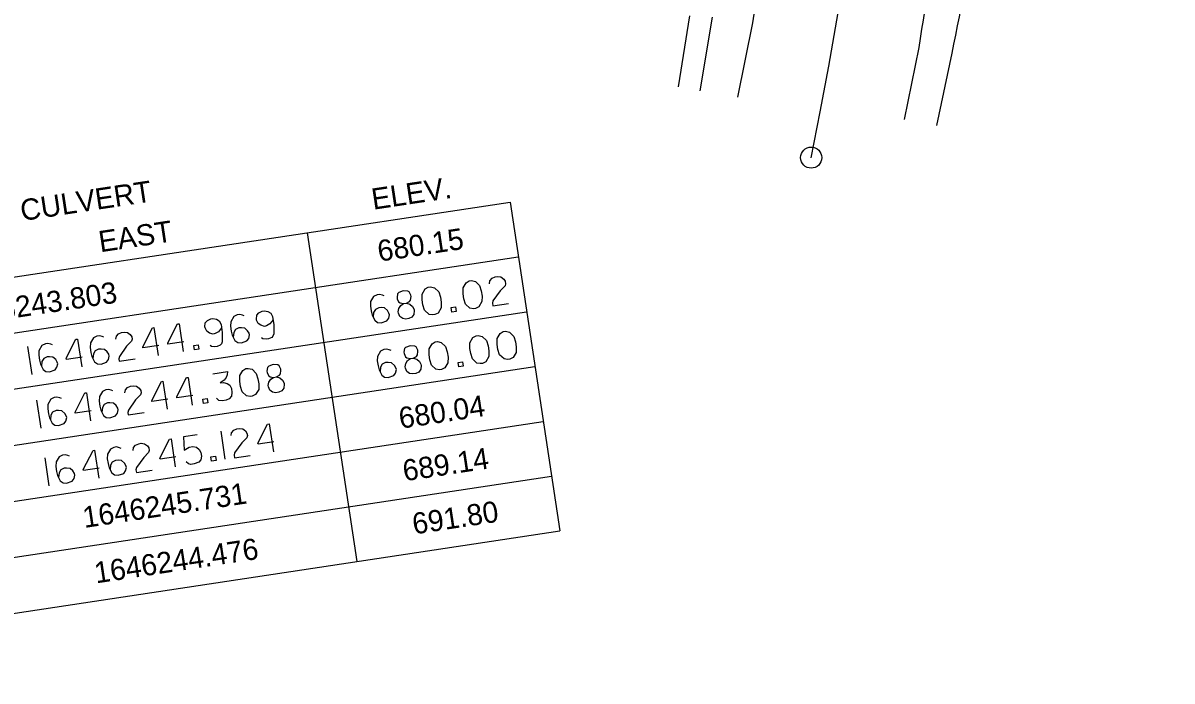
# Model space of a CAD drawing. Extents: x 1645945 to 2447332, y 713118 to 970361.
# Drawn here: x 1646189.7 to 1646352.4, y 969034 to 969127.2 of the extents above; entities that cross this region are included whole.
import ezdxf

# ---------------------------------------------------------------- set-up
doc = ezdxf.new("R2010")
doc.units = 0
for name, color, linetype in [('Exist Horizontal Alignment', 7, 'Continuous'), ('Exist Horizontal Alignment Station Label', 7, 'Continuous'), ('Exist Roads Curbs', 7, 'Continuous'), ('Exist Roads EOP', 7, 'Continuous'), ('Exist Roads EOT', 7, 'Continuous'), ('Exist Structure Major Bridge WW', 7, 'Continuous'), ('Exist Structure Major Bridge WW Text', 7, 'Continuous')]:
    doc.layers.add(name, color=color, linetype=linetype)

msp = doc.modelspace()

# ---------------------------------------------------------------- linework, layer by layer
at = {"layer": 'Exist Horizontal Alignment'}
msp.add_arc((1645516.89, 969265.29), 800, 348.6692, 18.755, dxfattribs=at)
at = {"layer": 'Exist Horizontal Alignment Station Label'}
msp.add_circle((1646301.3, 969108.12), 1.5, dxfattribs=at)
at = {"layer": 'Exist Roads Curbs'}
msp.add_line((1646282.51, 969118.14), (1646284.14, 969128.2), dxfattribs=at)
at = {"layer": 'Exist Roads EOP'}
for p, q in [((1646285.57, 969117.57), (1646287.33, 969128.01)), ((1646321.21, 969122.91), (1646319.04, 969112.67))]:
    msp.add_line(p, q, dxfattribs=at)
msp.add_spline([(1646379.88, 969432.02), (1646359.09, 969426.37), (1646353.34, 969423.7), (1646346.05, 969418.75), (1646333.89, 969406.7), (1646326.81, 969393.02), (1646325.09, 969385.45), (1646325.5, 969379.16), (1646330.03, 969336.13), (1646333.52, 969294.46), (1646334.18, 969250.57), (1646332.28, 969209.59), (1646328.48, 969164.09), (1646321.21, 969122.91)], degree=3, dxfattribs=at)
at = {"layer": 'Exist Roads EOT'}
for p, q in [((1646290.93, 969116.66), (1646293.03, 969127.18)), ((1646316.52, 969123.72), (1646314.47, 969113.51))]:
    msp.add_line(p, q, dxfattribs=at)
for points in [[(1646352.39, 969425.32), (1646344.68, 969420.87), (1646331.6, 969408.76), (1646323.81, 969394.56), (1646321.79, 969386.09), (1646321.5, 969379.49), (1646325.71, 969335.59), (1646328.02, 969294.74), (1646328.47, 969250.99), (1646326.96, 969209.87), (1646322.68, 969164.82), (1646316.52, 969123.72)], [(1646293.03, 969127.18), (1646298.98, 969166.96), (1646303.15, 969211.21), (1646304.61, 969249.63), (1646304.29, 969293.94), (1646302.47, 969332.58), (1646298.43, 969374.41), (1646292.35, 969414.45)]]:
    msp.add_spline(points, degree=3, dxfattribs=at)
at = {"layer": 'Exist Structure Major Bridge WW'}
for p, q in [((1646117.89, 969080.56), (1646258.66, 969101.81)), ((1646258.66, 969101.81), (1646265.69, 969055.26)), ((1646229.94, 969097.47), (1646236.96, 969050.93)), ((1646119.06, 969072.8), (1646259.83, 969094.05)), ((1646120.23, 969065.05), (1646261.01, 969086.29)), ((1646121.4, 969057.29), (1646262.18, 969078.54)), ((1646122.57, 969049.53), (1646263.35, 969070.78)), ((1646123.74, 969041.78), (1646264.52, 969063.02)), ((1646124.91, 969034.02), (1646265.69, 969055.26))]:
    msp.add_line(p, q, dxfattribs=at)
at = {"layer": 'Exist Structure Major Bridge WW Text'}
for p, q in [((1646191, 969077.42), (1646190.4, 969081.37)), ((1646192.27, 969069.82), (1646191.67, 969073.77)), ((1646218.34, 969065.43), (1646217.74, 969069.38)), ((1646193.42, 969061.67), (1646192.83, 969065.62))]:
    msp.add_line(p, q, dxfattribs=at)
for points in [[(1646252.88, 969090.67), (1646253.19, 969090.72), (1646253.75, 969090.58), (1646254.35, 969090), (1646254.59, 969089.24), (1646254.7, 969088.52), (1646254.69, 969087.73), (1646254.26, 969086.99), (1646253.79, 969086.76), (1646253.48, 969086.72), (1646252.99, 969086.8), (1646252.36, 969087.37), (1646252.11, 969088.13), (1646252.01, 969088.85), (1646252.01, 969089.68), (1646252.44, 969090.41), (1646252.88, 969090.67)], [(1646255.74, 969090.27), (1646255.81, 969090.67), (1646256.11, 969091.03), (1646256.55, 969091.22), (1646256.9, 969091.28), (1646257.38, 969091.22), (1646257.78, 969090.93), (1646257.98, 969090.61), (1646258.04, 969090.27), (1646257.95, 969089.97), (1646257.26, 969089.26), (1646256.24, 969087.83), (1646256.16, 969087.5), (1646256.22, 969087.13), (1646258.46, 969087.47)], [(1646240.84, 969088.57), (1646240.6, 969088.66), (1646240.2, 969088.76), (1646239.83, 969088.7), (1646239.35, 969088.47), (1646238.92, 969087.74), (1646238.89, 969087.09), (1646239, 969086.41), (1646239.15, 969085.83), (1646239.52, 969085.09), (1646239.91, 969084.79), (1646240.43, 969084.75), (1646241.21, 969085.02), (1646241.48, 969085.38), (1646241.59, 969085.88), (1646241.52, 969086.12), (1646241.31, 969086.47), (1646240.91, 969086.83), (1646240.42, 969086.88), (1646240.08, 969086.86), (1646239.6, 969086.63), (1646239.35, 969086.21), (1646239.28, 969085.56)], [(1646243.99, 969087.51), (1646244.43, 969087.74), (1646244.59, 969087.95), (1646244.65, 969088.44), (1646244.62, 969088.63), (1646244.39, 969089.1), (1646244.18, 969089.2), (1646243.54, 969089.26), (1646242.91, 969089.01), (1646242.74, 969088.85), (1646242.66, 969088.33), (1646242.68, 969088.14), (1646242.88, 969087.7), (1646243.1, 969087.54), (1646243.59, 969087.45), (1646243.99, 969087.51), (1646244.49, 969087.37), (1646244.86, 969087.04), (1646245.08, 969086.63), (1646245.1, 969086.47), (1646245.06, 969085.92), (1646244.77, 969085.53), (1646244.35, 969085.34), (1646243.91, 969085.27), (1646243.46, 969085.33), (1646243.07, 969085.62), (1646242.87, 969086.1), (1646242.84, 969086.29), (1646242.93, 969086.75), (1646243.18, 969087.17), (1646243.59, 969087.45)], [(1646247.09, 969089.8), (1646247.4, 969089.84), (1646247.96, 969089.7), (1646248.56, 969089.13), (1646248.8, 969088.37), (1646248.91, 969087.65), (1646248.9, 969086.85), (1646248.47, 969086.12), (1646247.99, 969085.89), (1646247.68, 969085.84), (1646247.19, 969085.93), (1646246.56, 969086.5), (1646246.32, 969087.26), (1646246.21, 969087.98), (1646246.22, 969088.8), (1646246.65, 969089.54), (1646247.09, 969089.8)], [(1646250.33, 969086.88), (1646250.95, 969086.97), (1646251.05, 969086.35), (1646250.42, 969086.25), (1646250.33, 969086.88)], [(1646217.81, 969084.04), (1646217.39, 969083.47), (1646216.92, 969083.21), (1646216.61, 969083.13), (1646216.11, 969083.28), (1646215.72, 969083.54), (1646215.49, 969084.01), (1646215.47, 969084.17), (1646215.51, 969084.72), (1646215.81, 969085.05), (1646216.29, 969085.28), (1646216.6, 969085.33), (1646217.09, 969085.24), (1646217.5, 969085.02), (1646217.74, 969084.51), (1646217.91, 969083.36), (1646217.91, 969082.94), (1646217.92, 969082.05), (1646217.81, 969081.75), (1646217.64, 969081.57), (1646217.19, 969081.37), (1646216.88, 969081.32), (1646216.4, 969081.38), (1646216.19, 969081.51)], [(1646221.03, 969085.71), (1646220.79, 969085.8), (1646220.4, 969085.9), (1646220.02, 969085.84), (1646219.55, 969085.61), (1646219.12, 969084.88), (1646219.09, 969084.24), (1646219.19, 969083.55), (1646219.34, 969082.97), (1646219.71, 969082.23), (1646220.1, 969081.94), (1646220.62, 969081.89), (1646221.41, 969082.17), (1646221.67, 969082.52), (1646221.79, 969083.02), (1646221.72, 969083.26), (1646221.51, 969083.61), (1646221.1, 969083.97), (1646220.62, 969084.02), (1646220.27, 969084), (1646219.79, 969083.77), (1646219.54, 969083.35), (1646219.48, 969082.7)], [(1646225.1, 969085.14), (1646224.67, 969084.57), (1646224.2, 969084.31), (1646223.9, 969084.23), (1646223.4, 969084.38), (1646223.01, 969084.64), (1646222.78, 969085.11), (1646222.75, 969085.27), (1646222.8, 969085.82), (1646223.1, 969086.15), (1646223.57, 969086.38), (1646223.88, 969086.43), (1646224.37, 969086.34), (1646224.79, 969086.12), (1646225.03, 969085.61), (1646225.2, 969084.46), (1646225.2, 969084.04), (1646225.21, 969083.15), (1646225.09, 969082.85), (1646224.93, 969082.67), (1646224.48, 969082.47), (1646224.17, 969082.42), (1646223.68, 969082.48), (1646223.47, 969082.61)], [(1646208.92, 969081.52), (1646206.68, 969081.19), (1646206.65, 969081.34), (1646208.03, 969084.03), (1646208.25, 969084.07), (1646208.85, 969080.11)], [(1646212.47, 969082.06), (1646210.23, 969081.72), (1646210.2, 969081.88), (1646211.58, 969084.57), (1646211.8, 969084.6), (1646212.4, 969080.65)], [(1646257.71, 969083.48), (1646258.03, 969083.53), (1646258.59, 969083.39), (1646259.19, 969082.81), (1646259.43, 969082.06), (1646259.54, 969081.34), (1646259.53, 969080.54), (1646259.1, 969079.81), (1646258.62, 969079.58), (1646258.31, 969079.53), (1646257.82, 969079.61), (1646257.19, 969080.19), (1646256.95, 969080.95), (1646256.84, 969081.67), (1646256.84, 969082.49), (1646257.28, 969083.23), (1646257.71, 969083.48)], [(1646198.08, 969079.89), (1646195.84, 969079.55), (1646195.82, 969079.71), (1646197.19, 969082.4), (1646197.41, 969082.43), (1646198.01, 969078.48)], [(1646201.16, 969082.71), (1646200.92, 969082.8), (1646200.53, 969082.9), (1646200.15, 969082.84), (1646199.68, 969082.61), (1646199.25, 969081.88), (1646199.22, 969081.24), (1646199.32, 969080.55), (1646199.47, 969079.97), (1646199.84, 969079.23), (1646200.23, 969078.94), (1646200.75, 969078.89), (1646201.54, 969079.17), (1646201.8, 969079.53), (1646201.92, 969080.02), (1646201.85, 969080.27), (1646201.64, 969080.62), (1646201.23, 969080.97), (1646200.75, 969081.02), (1646200.4, 969081), (1646199.92, 969080.77), (1646199.67, 969080.35), (1646199.61, 969079.7)], [(1646202.86, 969082.42), (1646202.93, 969082.82), (1646203.22, 969083.18), (1646203.67, 969083.38), (1646204.01, 969083.43), (1646204.5, 969083.37), (1646204.89, 969083.08), (1646205.1, 969082.76), (1646205.15, 969082.42), (1646205.07, 969082.12), (1646204.38, 969081.41), (1646203.36, 969079.98), (1646203.28, 969079.65), (1646203.33, 969079.28), (1646205.58, 969079.62)], [(1646248.06, 969082.03), (1646248.37, 969082.07), (1646248.93, 969081.94), (1646249.53, 969081.36), (1646249.77, 969080.6), (1646249.88, 969079.88), (1646249.87, 969079.08), (1646249.44, 969078.35), (1646248.97, 969078.12), (1646248.66, 969078.07), (1646248.17, 969078.16), (1646247.54, 969078.73), (1646247.3, 969079.49), (1646247.19, 969080.21), (1646247.19, 969081.04), (1646247.62, 969081.77), (1646248.06, 969082.03)], [(1646253.85, 969082.9), (1646254.16, 969082.95), (1646254.73, 969082.81), (1646255.32, 969082.23), (1646255.57, 969081.47), (1646255.67, 969080.76), (1646255.67, 969079.96), (1646255.24, 969079.22), (1646254.76, 969078.99), (1646254.45, 969078.95), (1646253.96, 969079.03), (1646253.33, 969079.61), (1646253.09, 969080.37), (1646252.98, 969081.08), (1646252.98, 969081.91), (1646253.41, 969082.64), (1646253.85, 969082.9)], [(1646193.87, 969081.61), (1646193.64, 969081.7), (1646193.24, 969081.8), (1646192.87, 969081.74), (1646192.39, 969081.51), (1646191.96, 969080.78), (1646191.93, 969080.14), (1646192.03, 969079.45), (1646192.18, 969078.87), (1646192.55, 969078.13), (1646192.95, 969077.84), (1646193.46, 969077.79), (1646194.25, 969078.07), (1646194.51, 969078.43), (1646194.63, 969078.92), (1646194.56, 969079.17), (1646194.35, 969079.52), (1646193.94, 969079.87), (1646193.46, 969079.92), (1646193.11, 969079.9), (1646192.64, 969079.67), (1646192.38, 969079.25), (1646192.32, 969078.6)], [(1646213.89, 969081.51), (1646214.51, 969081.6), (1646214.61, 969080.98), (1646213.99, 969080.89), (1646213.89, 969081.51)], [(1646241.81, 969080.8), (1646241.57, 969080.89), (1646241.18, 969080.99), (1646240.8, 969080.93), (1646240.33, 969080.7), (1646239.9, 969079.97), (1646239.87, 969079.33), (1646239.97, 969078.64), (1646240.12, 969078.06), (1646240.49, 969077.32), (1646240.88, 969077.03), (1646241.4, 969076.98), (1646242.19, 969077.26), (1646242.45, 969077.61), (1646242.57, 969078.11), (1646242.5, 969078.35), (1646242.29, 969078.7), (1646241.88, 969079.06), (1646241.4, 969079.11), (1646241.05, 969079.09), (1646240.57, 969078.86), (1646240.32, 969078.44), (1646240.26, 969077.79)], [(1646244.96, 969079.74), (1646245.41, 969079.97), (1646245.57, 969080.19), (1646245.62, 969080.67), (1646245.59, 969080.86), (1646245.36, 969081.33), (1646245.16, 969081.43), (1646244.51, 969081.49), (1646243.88, 969081.24), (1646243.71, 969081.08), (1646243.63, 969080.56), (1646243.66, 969080.38), (1646243.85, 969079.93), (1646244.07, 969079.77), (1646244.56, 969079.68), (1646244.96, 969079.74), (1646245.46, 969079.6), (1646245.83, 969079.27), (1646246.05, 969078.86), (1646246.08, 969078.7), (1646246.03, 969078.15), (1646245.74, 969077.76), (1646245.32, 969077.57), (1646244.89, 969077.5), (1646244.43, 969077.56), (1646244.04, 969077.85), (1646243.84, 969078.33), (1646243.81, 969078.52), (1646243.9, 969078.98), (1646244.16, 969079.4), (1646244.56, 969079.68)], [(1646225.58, 969077.07), (1646226.02, 969077.3), (1646226.18, 969077.51), (1646226.23, 969078), (1646226.2, 969078.19), (1646225.97, 969078.66), (1646225.77, 969078.76), (1646225.12, 969078.82), (1646224.49, 969078.57), (1646224.32, 969078.41), (1646224.24, 969077.89), (1646224.27, 969077.7), (1646224.46, 969077.26), (1646224.68, 969077.1), (1646225.17, 969077.01), (1646225.58, 969077.07), (1646226.08, 969076.93), (1646226.44, 969076.6), (1646226.66, 969076.19), (1646226.69, 969076.03), (1646226.64, 969075.48), (1646226.35, 969075.09), (1646225.94, 969074.9), (1646225.5, 969074.83), (1646225.04, 969074.89), (1646224.65, 969075.18), (1646224.45, 969075.66), (1646224.42, 969075.85), (1646224.51, 969076.31), (1646224.77, 969076.73), (1646225.17, 969077.01)], [(1646251.3, 969079.11), (1646251.93, 969079.2), (1646252.02, 969078.58), (1646251.4, 969078.49), (1646251.3, 969079.11)], [(1646213.74, 969074.46), (1646211.5, 969074.12), (1646211.47, 969074.28), (1646212.85, 969076.97), (1646213.07, 969077), (1646213.67, 969073.05)], [(1646216.59, 969077.53), (1646218.67, 969077.85), (1646218.62, 969077.36), (1646218.45, 969076.99), (1646218.19, 969076.63), (1646217.61, 969076.22), (1646218.08, 969076.29), (1646218.61, 969076.15), (1646218.97, 969075.89), (1646219.2, 969075.41), (1646219.28, 969074.88), (1646219.21, 969074.33), (1646218.91, 969073.96), (1646218.46, 969073.77), (1646217.93, 969073.69), (1646217.45, 969073.74), (1646217.11, 969074.04)], [(1646221.26, 969078.24), (1646221.57, 969078.28), (1646222.13, 969078.15), (1646222.73, 969077.57), (1646222.97, 969076.81), (1646223.08, 969076.09), (1646223.07, 969075.29), (1646222.64, 969074.56), (1646222.17, 969074.33), (1646221.86, 969074.28), (1646221.37, 969074.37), (1646220.74, 969074.94), (1646220.49, 969075.7), (1646220.39, 969076.42), (1646220.39, 969077.25), (1646220.82, 969077.98), (1646221.26, 969078.24)], [(1646204.13, 969074.82), (1646204.2, 969075.22), (1646204.49, 969075.58), (1646204.94, 969075.77), (1646205.28, 969075.83), (1646205.77, 969075.77), (1646206.16, 969075.48), (1646206.37, 969075.16), (1646206.42, 969074.82), (1646206.34, 969074.52), (1646205.65, 969073.81), (1646204.62, 969072.38), (1646204.55, 969072.05), (1646204.6, 969071.68), (1646206.84, 969072.02)], [(1646210.19, 969073.92), (1646207.95, 969073.58), (1646207.92, 969073.74), (1646209.3, 969076.43), (1646209.52, 969076.47), (1646210.11, 969072.51)], [(1646195.14, 969074.01), (1646194.9, 969074.1), (1646194.51, 969074.2), (1646194.13, 969074.14), (1646193.66, 969073.91), (1646193.23, 969073.18), (1646193.2, 969072.54), (1646193.3, 969071.85), (1646193.45, 969071.27), (1646193.82, 969070.53), (1646194.21, 969070.24), (1646194.73, 969070.19), (1646195.52, 969070.47), (1646195.78, 969070.82), (1646195.9, 969071.32), (1646195.83, 969071.56), (1646195.62, 969071.91), (1646195.21, 969072.27), (1646194.73, 969072.32), (1646194.38, 969072.3), (1646193.9, 969072.07), (1646193.65, 969071.65), (1646193.59, 969071)], [(1646199.35, 969072.29), (1646197.11, 969071.95), (1646197.08, 969072.1), (1646198.46, 969074.8), (1646198.68, 969074.83), (1646199.28, 969070.87)], [(1646202.43, 969075.11), (1646202.19, 969075.2), (1646201.79, 969075.3), (1646201.42, 969075.24), (1646200.95, 969075.01), (1646200.52, 969074.28), (1646200.48, 969073.64), (1646200.59, 969072.95), (1646200.74, 969072.37), (1646201.11, 969071.63), (1646201.5, 969071.34), (1646202.02, 969071.29), (1646202.8, 969071.57), (1646203.07, 969071.92), (1646203.18, 969072.42), (1646203.12, 969072.66), (1646202.9, 969073.01), (1646202.5, 969073.37), (1646202.01, 969073.42), (1646201.67, 969073.4), (1646201.19, 969073.17), (1646200.94, 969072.75), (1646200.88, 969072.1)], [(1646215.16, 969073.91), (1646215.78, 969074), (1646215.88, 969073.38), (1646215.25, 969073.29), (1646215.16, 969073.91)], [(1646214.35, 969068.87), (1646212.42, 969068.58), (1646212.54, 969066.69), (1646213.24, 969067.14), (1646213.77, 969067.22), (1646214.29, 969067.11), (1646214.66, 969066.81), (1646214.88, 969066.37), (1646214.96, 969065.87), (1646214.88, 969065.35), (1646214.61, 969064.99), (1646213.95, 969064.76), (1646213.48, 969064.69), (1646213.12, 969064.77), (1646212.79, 969065.07)], [(1646219.17, 969068.77), (1646219.24, 969069.16), (1646219.54, 969069.53), (1646219.98, 969069.72), (1646220.33, 969069.77), (1646220.81, 969069.72), (1646221.21, 969069.43), (1646221.41, 969069.11), (1646221.47, 969068.77), (1646221.38, 969068.47), (1646220.69, 969067.76), (1646219.67, 969066.33), (1646219.59, 969066), (1646219.65, 969065.62), (1646221.89, 969065.96)], [(1646225.23, 969067.87), (1646222.99, 969067.53), (1646222.97, 969067.69), (1646224.34, 969070.38), (1646224.56, 969070.41), (1646225.16, 969066.46)], [(1646205.28, 969066.67), (1646205.35, 969067.07), (1646205.65, 969067.43), (1646206.09, 969067.62), (1646206.44, 969067.68), (1646206.92, 969067.62), (1646207.32, 969067.33), (1646207.52, 969067.01), (1646207.58, 969066.67), (1646207.49, 969066.37), (1646206.8, 969065.66), (1646205.78, 969064.23), (1646205.7, 969063.9), (1646205.76, 969063.53), (1646208, 969063.87)], [(1646211.34, 969065.77), (1646209.1, 969065.43), (1646209.08, 969065.59), (1646210.45, 969068.28), (1646210.67, 969068.31), (1646211.27, 969064.36)], [(1646196.3, 969065.86), (1646196.06, 969065.95), (1646195.66, 969066.05), (1646195.29, 969065.99), (1646194.81, 969065.76), (1646194.38, 969065.03), (1646194.35, 969064.39), (1646194.45, 969063.7), (1646194.61, 969063.12), (1646194.97, 969062.38), (1646195.37, 969062.09), (1646195.88, 969062.04), (1646196.67, 969062.32), (1646196.94, 969062.67), (1646197.05, 969063.17), (1646196.98, 969063.41), (1646196.77, 969063.76), (1646196.37, 969064.12), (1646195.88, 969064.17), (1646195.53, 969064.15), (1646195.06, 969063.92), (1646194.8, 969063.5), (1646194.74, 969062.85)], [(1646200.5, 969064.14), (1646198.26, 969063.8), (1646198.24, 969063.95), (1646199.62, 969066.65), (1646199.83, 969066.68), (1646200.43, 969062.72)], [(1646203.58, 969066.96), (1646203.35, 969067.05), (1646202.95, 969067.15), (1646202.58, 969067.09), (1646202.1, 969066.86), (1646201.67, 969066.13), (1646201.64, 969065.49), (1646201.74, 969064.8), (1646201.89, 969064.22), (1646202.26, 969063.48), (1646202.65, 969063.19), (1646203.17, 969063.14), (1646203.96, 969063.42), (1646204.22, 969063.77), (1646204.34, 969064.27), (1646204.27, 969064.51), (1646204.06, 969064.86), (1646203.65, 969065.22), (1646203.17, 969065.27), (1646202.82, 969065.25), (1646202.35, 969065.02), (1646202.09, 969064.6), (1646202.03, 969063.95)], [(1646216.31, 969065.76), (1646216.94, 969065.85), (1646217.03, 969065.23), (1646216.41, 969065.14), (1646216.31, 969065.76)]]:
    msp.add_lwpolyline(points, dxfattribs=at)

# ---------------------------------------------------------------- texts
for s, p in [("2 @ 9' X 10' BOX CULVERT", (1646157.56, 969094.3)), ('ELEV.', (1646239.29, 969100.73)), ('EAST', (1646200.65, 969094.71)), ('680.15', (1646240.13, 969093.38)), ('969167.980   1646243.803', (1646155.77, 969080.46)), ('680.04     ', (1646243.15, 969069.73)), ('689.14', (1646243.7, 969062.29)), ('1646245.731', (1646198.39, 969055.68)), ('691.80     ', (1646245.06, 969054.76)), ('1646244.476 ', (1646200.04, 969047.83))]:
    msp.add_text(s, height=3, rotation=8.5827, dxfattribs=at).set_placement(p)

doc.saveas('drawing.dxf')
